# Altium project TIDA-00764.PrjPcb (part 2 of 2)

## Sheet TIDA-00764_Power_Stage.SchDoc: Power Stage
size 431 x 279 mm; Date: Not shown in title block; ApprovedBy: Not shown in title block; CheckedBy: Not shown in title block; Author: Not shown in title block; CompanyName: Not shown in title block; DrawnBy: Tobias Puetz; Engineer: Not shown in title block; Organization: Not shown in title block; Address1: Not shown in title block; Address2: Not shown in title block; Address3: Not shown in title block; Address4: Not shown in title block; DocumentNumber: 4; Revision: Use project parameter SCH_Rev; SheetNumber: 4; SheetTotal: 10; PageSetup: Record=PageOptions¦CenterHorizontal=True¦CenterVertical=True¦PrintScale=0.66¦XCorrection=1.00¦YCorrection=1.00¦PrintKind=0¦BorderSize=5000000¦LeftOffset=0¦BottomOffset=0¦Orientation=2¦PaperLength=1000¦PaperWidth=1000¦Scale=100¦PaperSource=15¦PrintQuality=600¦MediaType=1¦DitherType=10¦PrintScaleMode=1¦PaperKind=Letter
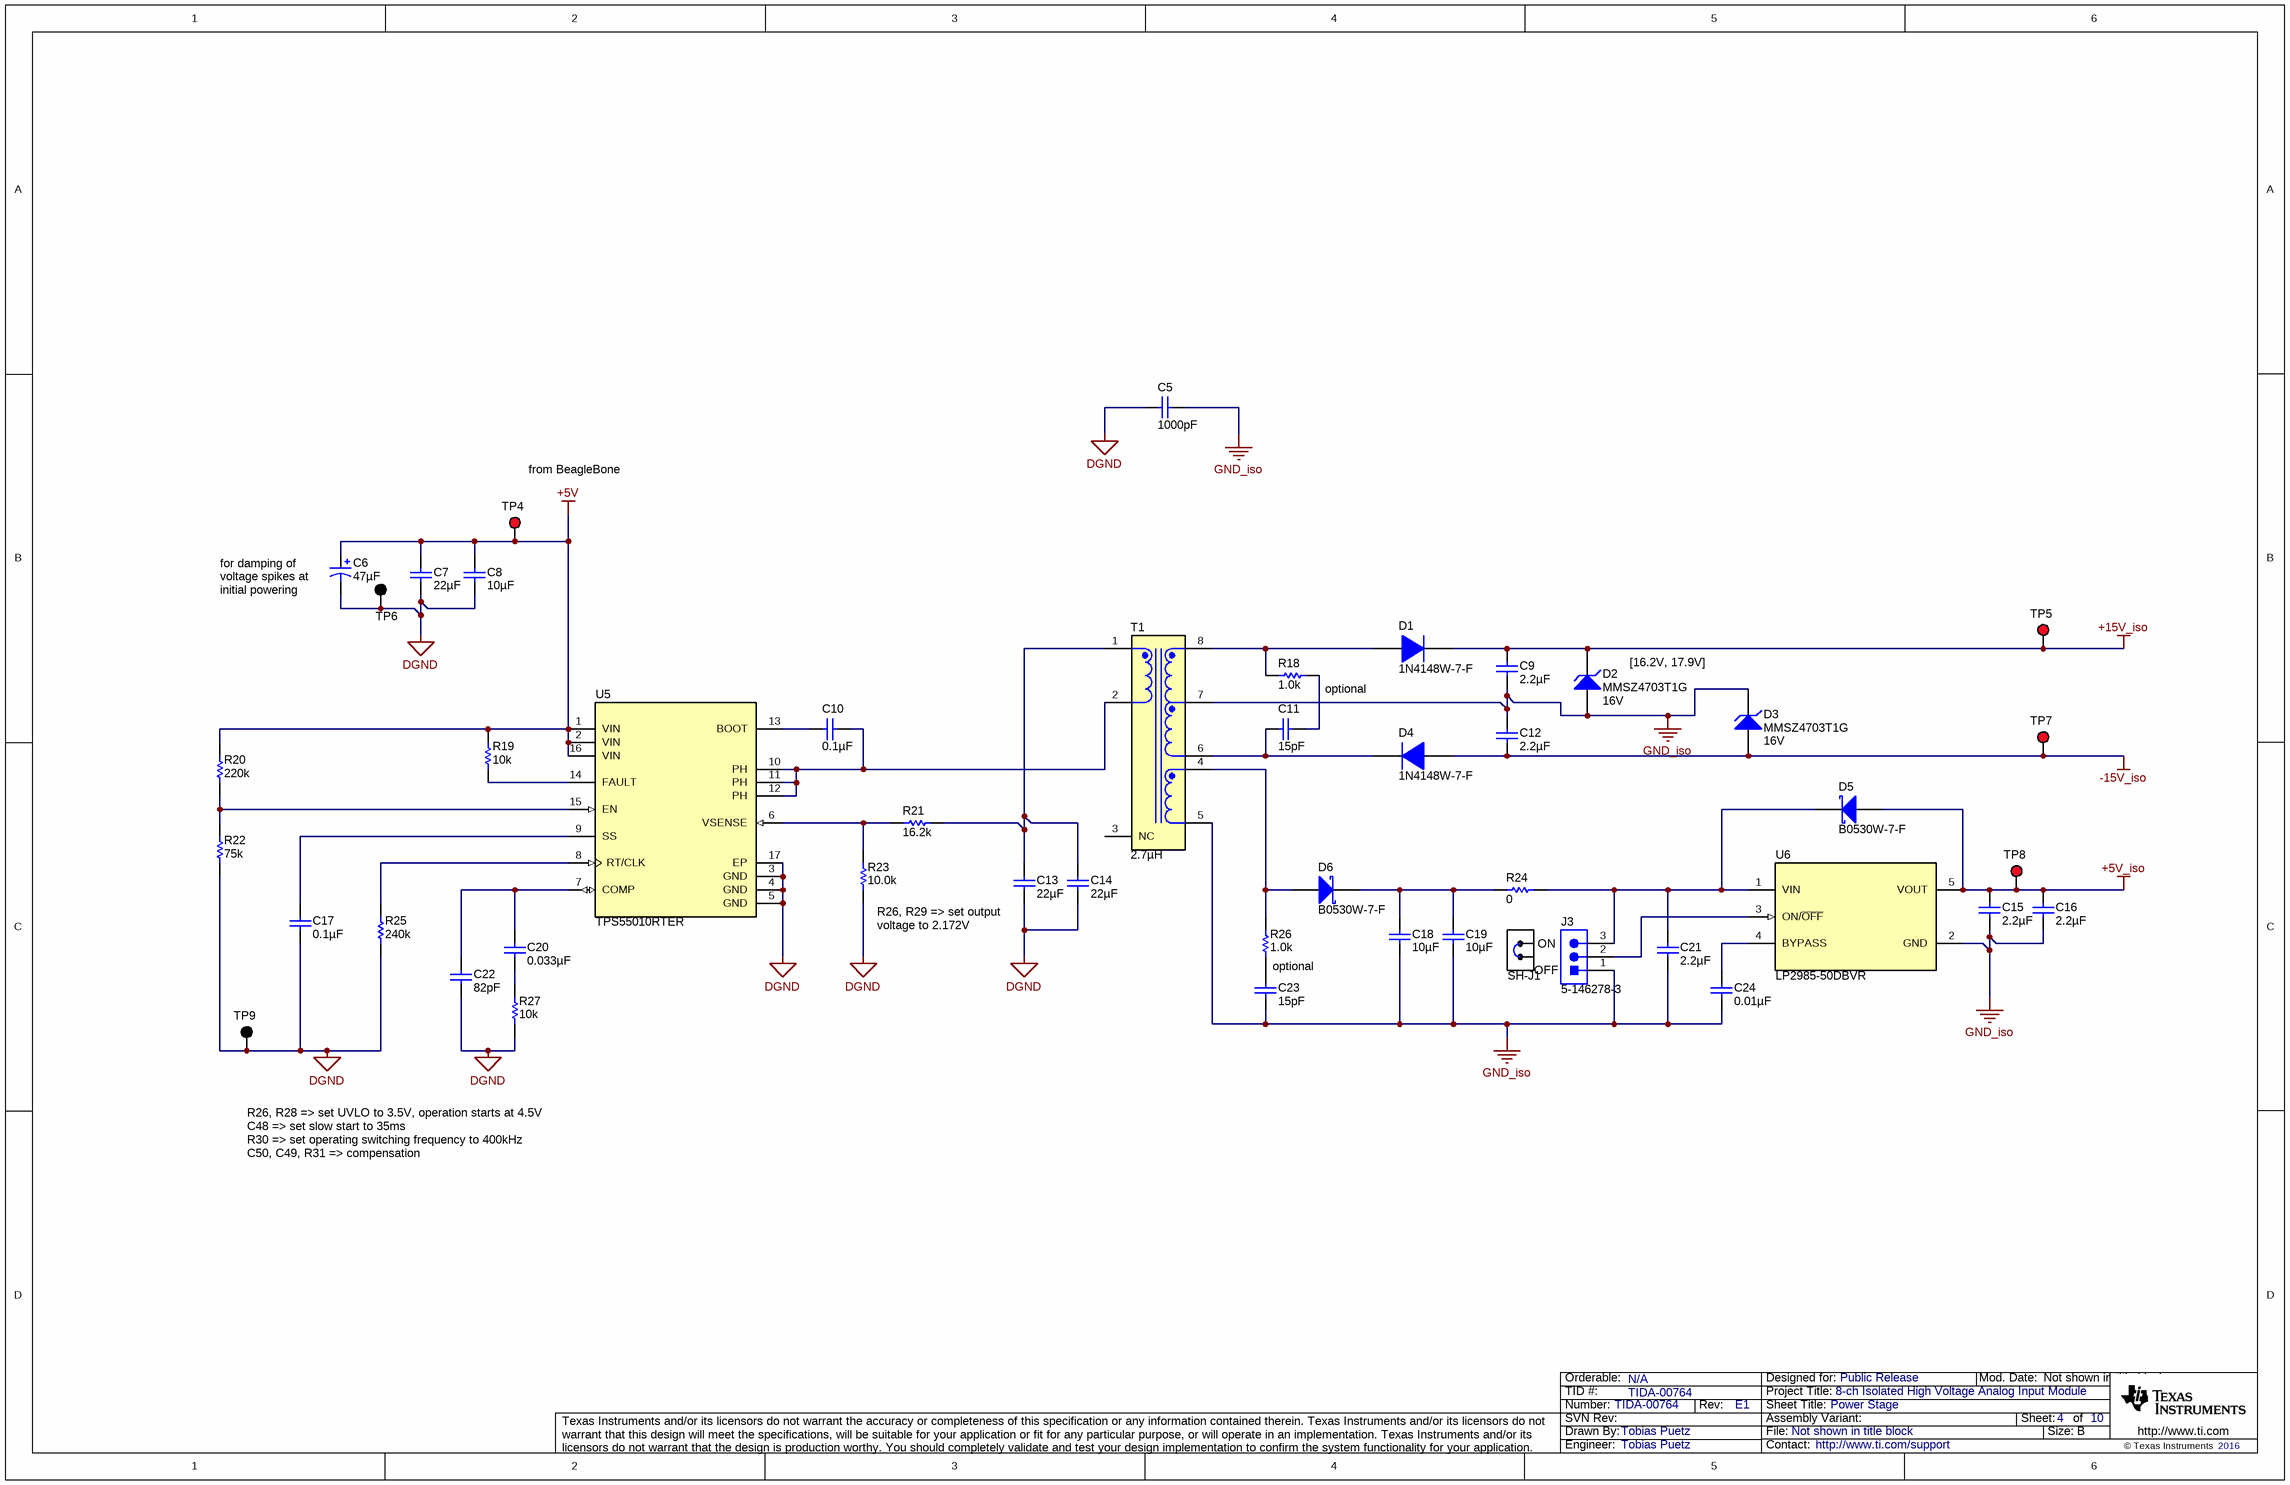
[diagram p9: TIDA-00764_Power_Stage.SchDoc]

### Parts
C5  ValueDisplayed: 1000pF  [1206_190]  (hidden comment: 202R18W102KV4E)
C6  ValueDisplayed: 47µF  [CAPPRD200W50D500H1100]  (hidden comment: ECA-1VM470)
C7  ValueDisplayed: 22µF  [1206_180]  (hidden comment: GRM31CR71A226KE15L)
C8  ValueDisplayed: 10µF  [0805_HV]  (hidden comment: C2012X7R1A106K125AC)
C9  ValueDisplayed: 2.2µF  [1206_180]  (hidden comment: GRM31CR71H225KA88L)
C10  ValueDisplayed: 0.1µF  [0603]  (hidden comment: C1608X7R1C104K)
C11  ValueDisplayed: 15pF  [0603]  (hidden comment: C1608C0G1H150J)
C12  ValueDisplayed: 2.2µF  [1206_180]  (hidden comment: GRM31CR71H225KA88L)
C13  ValueDisplayed: 22µF  [1206_180]  (hidden comment: GRM31CR71A226KE15L)
C14  ValueDisplayed: 22µF  [1206_180]  (hidden comment: GRM31CR71A226KE15L)
C15  ValueDisplayed: 2.2µF  [0603]  (hidden comment: GRM188R71A225KE15D)
C16  ValueDisplayed: 2.2µF  [0603]  (hidden comment: GRM188R71A225KE15D)
C17  ValueDisplayed: 0.1µF  [0603]  (hidden comment: C1608X7R1C104K)
C18  ValueDisplayed: 10µF  [0805_HV]  (hidden comment: C2012X7R1A106K125AC)
C19  ValueDisplayed: 10µF  [0805_HV]  (hidden comment: C2012X7R1A106K125AC)
C20  ValueDisplayed: 0.033µF  [0603]  (hidden comment: GRM188R71H333KA61D)
C21  ValueDisplayed: 2.2µF  [0603]  (hidden comment: GRM188R71A225KE15D)
C22  ValueDisplayed: 82pF  [0603]  (hidden comment: GRM1885C1H820JA01D)
C23  ValueDisplayed: 15pF  [0603]  (hidden comment: C1608C0G1H150J)
C24  ValueDisplayed: 0.01µF  [0603]  (hidden comment: GRM188R71C103KA01D)
D1  1N4148W-7-F  [SOD-123]
D2  MMSZ4703T1G  value 16V  [SOD-123]
D3  MMSZ4703T1G  value 16V  [SOD-123]
D4  1N4148W-7-F  [SOD-123]
D5  B0530W-7-F  [SOD-123]
D6  B0530W-7-F  [SOD-123]
J3  5-146278-3  [TE_5-146278-3]
R18  ValueDisplayed: 1.0k  [0805_HV]  (hidden comment: ERJ-6GEYJ102V)
R19  ValueDisplayed: 10k  [0603]  (hidden comment: CRCW060310K0JNEA)
R20  ValueDisplayed: 220k  [0603]  (hidden comment: CRCW0603220KJNEA)
R21  ValueDisplayed: 16.2k  [0603]  (hidden comment: CRCW060316K2FKEA)
R22  ValueDisplayed: 75k  [0603]  (hidden comment: CRCW060375K0JNEA)
R23  ValueDisplayed: 10.0k  [0603]  (hidden comment: CRCW060310K0FKEA)
R24  ValueDisplayed: 0  [0603]  (hidden comment: CRCW06030000Z0EA)
R25  ValueDisplayed: 240k  [0603]  (hidden comment: CRCW0603240KJNEA)
R26  ValueDisplayed: 1.0k  [0805_HV]  (hidden comment: ERJ-6GEYJ102V)
R27  ValueDisplayed: 10k  [0603]  (hidden comment: CRCW060310K0JNEA)
SH-J1  60900213421  [Wurth_60900213421]  (value not drawn)
T1  ValueDisplayed: 2.7µH  [Wurth_750316170]  (hidden comment: 750316170)
TP4  5000  [Keystone5000]  (value not drawn)
TP5  5000  [Keystone5000]  (value not drawn)
TP6  5001  [Keystone5001]  (value not drawn)
TP7  5000  [Keystone5000]  (value not drawn)
TP8  5000  [Keystone5000]  (value not drawn)
TP9  5001  [Keystone5001]  (value not drawn)
U5  TPS55010RTER  [RTE0016C]
U6  LP2985-50DBVR  [DBV0005A_N]

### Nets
+5V: C6.1(+) C7.1 C8.2 R19.2 R20.2 TP4.1 U5.1(VIN) U5.2(VIN) U5.16(VIN)
+5V_iso: C15.1 C16.1 D5.2(A) TP8.1 U6.5(VOUT)
+15V_iso: C9.1 D1.1(K) D2.1(K) TP5.1
-15V_iso: C12.2 D3.2(A) D4.2(A) TP7.1
DGND: C5.2 C6.2(-) C7.2 C8.1 C13.2 C14.2 C17.1 C22.1 R22.1 R23.1 R25.1 R27.1 TP6.1 TP9.1 U5.3(GND) U5.4(GND) U5.5(GND) U5.17(EP)
GND_iso: C5.1 C9.2 C12.1 C15.2 C16.2 C18.2 C19.1 C21.2 C23.1 C24.2 D2.2(A) D3.1(K) J3.1 T1.5 T1.7 U6.2(GND)
NetC10_1: C10.1 T1.2 U5.10(PH) U5.11(PH) U5.12(PH)
NetC10_2: C10.2 U5.13(BOOT)
NetC11_1: C11.1 R18.1
NetC11_2: C11.2 D4.1(K) T1.6
NetC13_1: C13.1 C14.1 R21.1 T1.1
NetC17_2: C17.2 U5.9(SS)
NetC18_1: C18.1 C19.2 D6.1(K) R24.1
NetC20_1: C20.1 C22.2 U5.7(COMP)
NetC20_2: C20.2 R27.2
NetC21_1: C21.1 D5.1(K) J3.3 R24.2 U6.1(VIN)
NetC23_2: C23.2 R26.1
NetC24_1: C24.1 U6.4(BYPASS)
NetD1_2: D1.2(A) R18.2 T1.8
NetD6_2: D6.2(A) R26.2 T1.4
NetJ3_2: J3.2 U6.3(ON/~{OFF})
NetR19_1: R19.1 U5.14(FAULT)
NetR20_1: R20.1 R22.2 U5.15(EN)
NetR21_2: R21.2 R23.2 U5.6(VSENSE)
NetR25_2: R25.2 U5.8(RT/CLK)

Not connected (* = marked no-connect by the designer): T1 3(NC)

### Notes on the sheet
- from BeagleBone
- (near C6) for damping of voltage spikes at initial powering
- (near R18) optional
- [16.2V, 17.9V]
- R26, R29 => set output voltage to 2.172V
- (near R26) optional
- ON
- OFF
- R26, R28 => set UVLO to 3.5V, operation starts at 4.5V
  C48 => set slow start to 35ms
  R30 => set operating switching frequency to 400kHz
  C50, C49, R31 => compensation

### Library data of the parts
C5 = 202R18W102KV4E: CAP, CERM, 1000 pF, 2000 V, +/- 10%, X7R, 1206_190; Manufacturer: Johanson Technology; Polarized: N; CompType: Capacitor; Value: 1000pF; U/M: EA; Cap_F: 0.000000001; Tolerance_%: 10; Value1: Unknown; VDC_V: 2000; Value2: 2000V; TaMin_C: -55; TaMax_C: 125; Cap_Case: 1206; AEC Category: Q200
C6 = ECA-1VM470: CAP, AL, 47 µF, 35 V, +/- 20%, TH; Manufacturer: Panasonic; Polarized: Y; CompType: Capacitor; Value: 47uF; U/M: EA; Cap_F: 0.000047; Tolerance_%: 20; Value1: Unknown; VDC_V: 35; Value2: 35V; IRMS_A: 0.13; TaMin_C: -40; TaMax_C: 85; Cap_Case: RCAP, 5x11mm; AEC Category: Q200; AEC Qualified: N
C7 C13 C14 = GRM31CR71A226KE15L: CAP, CERM, 22 µF, 10 V, +/- 10%, X7R, 1206; Manufacturer: MuRata; Polarized: N; CompType: Capacitor; Value: 22uF; U/M: EA; Cap_F: 0.000022; Tolerance_%: 10; Value1: Unknown; Value2: 10V; TaMin_C: -55; TaMax_C: 125; Cap_Case: 1206; AEC Category: Q200
C8 C18 C19 = C2012X7R1A106K125AC: CAP, CERM, 10 µF, 10 V, +/- 10%, X7R, 0805; Manufacturer: TDK; Polarized: N; CompType: Capacitor; Value: 10uF; U/M: EA; Cap_F: 0.00001; Tolerance_%: 10; Value1: Unknown; Value2: 10V; TaMin_C: -55; TaMax_C: 125; Cap_Case: 0805; AEC Category: Q200
C9 C12 = GRM31CR71H225KA88L: CAP, CERM, 2.2 µF, 50 V, +/- 10%, X7R, 1206; Manufacturer: MuRata; Polarized: N; CompType: Capacitor; Value: 2.2uF; U/M: EA; Cap_F: 0.0000022; Tolerance_%: 10; Value1: Unknown; VDC_V: 50; Value2: 50V; TaMin_C: -55; TaMax_C: 125; Cap_Case: 1206; AEC Category: Q200
C10 C17 = C1608X7R1C104K: CAP, CERM, 0.1 µF, 16 V, +/- 10%, X7R, 0603; Manufacturer: TDK; Polarized: N; CompType: Capacitor; Value: 0.1uF; U/M: EA; Cap_F: 0.0000001; Tolerance_%: 10; ESR_ohm: 0.017; Value1: 0.017 ohm; VDC_V: 16; Value2: 16V; TaMin_C: -55; TaMax_C: 125; AEC Category: Q200
C11 C23 = C1608C0G1H150J: CAP, CERM, 15 pF, 50 V, +/- 5%, C0G/NP0, 0603; Manufacturer: TDK; Polarized: N; CompType: Capacitor; Value: 15pF; U/M: EA; Cap_F: 0.000000000015; Tolerance_%: 5; ESR_ohm: 0.46; Value1: 0.46 ohm; VDC_V: 50; Value2: 50V; TaMin_C: -55; TaMax_C: 125; AEC Category: Q200
C15 C16 C21 = GRM188R71A225KE15D: CAP, CERM, 2.2 µF, 10 V, +/- 10%, X7R, 0603; Manufacturer: MuRata; Polarized: N; CompType: Capacitor; Value: 2.2uF; U/M: EA; Cap_F: 0.0000022; Tolerance_%: 10; ESR_ohm: 0.009; Value1: 0.009 ohm; Value2: 10V; TaMin_C: -55; TaMax_C: 125; AEC Category: Q200
C20 = GRM188R71H333KA61D: CAP, CERM, 0.033 µF, 50 V, +/- 10%, X7R, 0603; Manufacturer: MuRata; Polarized: N; CompType: Capacitor; Value: 0.033uF; U/M: EA; Cap_F: 0.000000033; Tolerance_%: 10; Value1: Unknown; VDC_V: 50; Value2: 50V; TaMin_C: -55; TaMax_C: 125; AEC Category: Q200
C22 = GRM1885C1H820JA01D: CAP, CERM, 82 pF, 50 V, +/- 5%, C0G/NP0, 0603; Manufacturer: MuRata; Polarized: N; CompType: Capacitor; Value: 82pF; U/M: EA; Cap_F: 0.000000000082; Tolerance_%: 5; Value1: Unknown; VDC_V: 50; Value2: 50V; TaMin_C: -55; TaMax_C: 125; AEC Category: Q200
C24 = GRM188R71C103KA01D: CAP, CERM, 0.01 µF, 16 V, +/- 10%, X7R, 0603; Manufacturer: MuRata; Polarized: N; CompType: Capacitor; Value: 0.01uF; U/M: EA; Cap_F: 0.00000001; Tolerance_%: 10; Value1: Unknown; VDC_V: 16; Value2: 16V; TaMin_C: -55; TaMax_C: 125; AEC Category: Q200
D1 D4 = 1N4148W-7-F: Diode, Ultrafast, 100 V, 0.15 A, SOD-123; Manufacturer: Diodes Inc.; U/M: EA; Vf_V: 1.25; Value: 100V; Value1: 0.15A; Value2: 1.25V; Io_A: 0.15; Vr_V: 100; TJmax_C: 150; AEC Category: Q101
D2 D3 = MMSZ4703T1G: Diode, Zener, 16 V, 500 mW, SOD-123; Manufacturer: ON Semiconductor; SymbolCreator: a0412235; U/M: EA; Power_W: 0.5; Vz_V: 16; Value1: 0.5W; RJA_CperW: 340; AEC Category: Q101
D5 D6 = B0530W-7-F: Diode, Schottky, 30 V, 0.5 A, SOD-123; Manufacturer: Diodes Inc.; U/M: EA; Vf_V: 0.43; Value: 30V; Value1: 0.5A; Value2: 0.43V; Io_A: 0.5; Vr_V: 30; TJmax_C: 125; AEC Category: Q101
J3 = 5-146278-3: Header, 100mil, 3x1, Tin, TH; Manufacturer: TE Connectivity; SymbolCreator: a0799628
R18 R26 = ERJ-6GEYJ102V: RES, 1.0 k, 5%, 0.125 W, 0805; Manufacturer: Panasonic; CompType: Resistor; Value: 1.0k; Res_ohm: 1000; Value_Code: 1k00; Tolerance_%: 5; Power_W: 0.125; Value2: 0.125W; VDC_V: 150; TempCo: 200 ppm/C; EIA_Code: E24; U/M: EA; AEC Category: Q200
R19 R27 = CRCW060310K0JNEA: RES, 10 k, 5%, 0.1 W, 0603; Manufacturer: Vishay-Dale; CompType: Resistor; Value: 10k; Res_ohm: 10000; Value_Code: 10k0; Tolerance_%: 5; Power_W: 0.1; Value2: 0.1W; VDC_V: 75; TempCo: 200 ppm/C; EIA_Code: E24; U/M: EA; AEC Category: Q200
R20 = CRCW0603220KJNEA: RES, 220 k, 5%, 0.1 W, 0603; Manufacturer: Vishay-Dale; CompType: Resistor; Value: 220k; Res_ohm: 220000; Tolerance_%: 5; Power_W: 0.1; Value2: 0.1W; VDC_V: 75; TempCo: 200 ppm/C; EIA_Code: E24; U/M: EA; AEC Category: Q200
R21 = CRCW060316K2FKEA: RES, 16.2 k, 1%, 0.1 W, 0603; Manufacturer: Vishay-Dale; CompType: Resistor; Value: 16.2k; Res_ohm: 16200; Value_Code: 16k2; Tolerance_%: 1; Power_W: 0.1; Value2: 0.1W; VDC_V: 75; TempCo: 100 ppm/C; EIA_Code: E96; U/M: EA; AEC Category: Q200
R22 = CRCW060375K0JNEA: RES, 75 k, 5%, 0.1 W, 0603; Manufacturer: Vishay-Dale; CompType: Resistor; Value: 75k; Res_ohm: 75000; Value_Code: 75k0; Tolerance_%: 5; Power_W: 0.1; Value2: 0.1W; VDC_V: 75; TempCo: 200 ppm/C; EIA_Code: E24; U/M: EA; AEC Category: Q200
R23 = CRCW060310K0FKEA: RES, 10.0 k, 1%, 0.1 W, 0603; Manufacturer: Vishay-Dale; CompType: Resistor; Value: 10.0k; Res_ohm: 10000; Value_Code: 10k0; Tolerance_%: 1; Power_W: 0.1; Value2: 0.1W; VDC_V: 75; TempCo: 100 ppm/C; EIA_Code: E96; U/M: EA; AEC Category: Q200
R24 = CRCW06030000Z0EA: RES, 0, 5%, 0.1 W, 0603; Manufacturer: Vishay-Dale; CompType: Resistor; Value: 0; Value_Code: 0000; Tolerance_%: 5; Power_W: 0.1; Value2: 0.1W; VDC_V: 75; TempCo: 200 ppm/C; EIA_Code: E24; U/M: EA; AEC Category: Q200
R25 = CRCW0603240KJNEA: RES, 240 k, 5%, 0.1 W, 0603; Manufacturer: Vishay-Dale; CompType: Resistor; Value: 240k; Res_ohm: 240000; Tolerance_%: 5; Power_W: 0.1; Value2: 0.1W; VDC_V: 75; TempCo: 200 ppm/C; EIA_Code: E24; U/M: EA; AEC Category: Q200
SH-J1 = 60900213421: Shunt, 2.54mm, Gold, Black; Manufacturer: Wurth Elektronik
T1 = 750316170: Transformer, 2.7 uH, SMT; Manufacturer: Wurth Elektronik; SymbolCreator: Altium; Value: 2.7uH; Lp: 2.7; DCR_ohm: 0.015; Ns1toNp: 8; Ns3toNp: 3; Rs1: 2.1; Rs3: 0.295
TP4 TP5 TP7 TP8 = 5000: Test Point, Miniature, Red, TH; Manufacturer: Keystone; CompType: Test Point Loop; ContactFinish: Silver
TP6 TP9 = 5001: Test Point, Miniature, Black, TH; Manufacturer: Keystone; CompType: Test Point Loop; ContactFinish: Silver
U5 = TPS55010RTER: 2.95V To 6V Input, 2W, Isolated DC/DC Converter with Integrated FETs, RTE0016C; Manufacturer: Texas Instruments; SymbolCreator: Altium; CompType: IC; U/M: EA
U6 = LP2985-50DBVR: 150-mA Low-noise Low-dropout Regulator With Shutdown, DBV0005A; Alternate PartNumber: LP2985-50DBVT; Manufacturer: Texas Instruments; SymbolCreator: Altium; CompType: IC; U/M: EA

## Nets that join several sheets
+5V: TIDA-00764_Cape (NT1.2), TIDA-00764_Digital_Isolation (6 pins), TIDA-00764_Power_Stage (9 pins)
+5V_iso: TIDA-00764_MUX_Stage (9 pins), TIDA-00764_Digital_Isolation (7 pins), TIDA-00764_Power_Stage (5 pins)
+15V_iso: U_TIDA-00764_Signal_Chain/Channel_Inputs/CMCh1 (C30_CMCh1.2 C31_CMCh1.1 U7_CMCh1.7), U_TIDA-00764_Signal_Chain/Channel_Inputs/CMCh3 (C30_CMCh3.2 C31_CMCh3.1 U7_CMCh3.7), U_TIDA-00764_Signal_Chain/Channel_Inputs/CMCh2 (C30_CMCh2.2 C31_CMCh2.1 U7_CMCh2.7), U_TIDA-00764_Signal_Chain/Channel_Inputs/CMCh4 (C30_CMCh4.2 C31_CMCh4.1 U7_CMCh4.7), TIDA-00764_MUX_Stage (C44.1 C45.2 U11.13 U13.5), TIDA-00764_Power_Stage (C9.1 D1.1 D2.1 TP5.1)
-15V_iso: U_TIDA-00764_Signal_Chain/Channel_Inputs/CMCh1 (C25_CMCh1.1 C26_CMCh1.2 U7_CMCh1.4), U_TIDA-00764_Signal_Chain/Channel_Inputs/CMCh3 (C25_CMCh3.1 C26_CMCh3.2 U7_CMCh3.4), U_TIDA-00764_Signal_Chain/Channel_Inputs/CMCh2 (C25_CMCh2.1 C26_CMCh2.2 U7_CMCh2.4), U_TIDA-00764_Signal_Chain/Channel_Inputs/CMCh4 (C25_CMCh4.1 C26_CMCh4.2 U7_CMCh4.4), TIDA-00764_MUX_Stage (C39.2 U11.3 U13.2), TIDA-00764_Power_Stage (C12.2 D3.2 D4.2 TP7.1)
DGND: TIDA-00764_Cape (21 pins), TIDA-00764_Digital_Isolation (7 pins), TIDA-00764_Power_Stage (18 pins)
GND_iso: TIDA-00764_Signal_Chain (5 pins), U_TIDA-00764_Signal_Chain/Channel_Inputs/CMCh1 (11 pins), U_TIDA-00764_Signal_Chain/Channel_Inputs/CMCh3 (11 pins), U_TIDA-00764_Signal_Chain/Channel_Inputs/CMCh2 (11 pins), U_TIDA-00764_Signal_Chain/Channel_Inputs/CMCh4 (11 pins), U_TIDA-00764_Signal_Chain/Channel_Inputs/NoCMCh1 (C32_NoCMCh1.2 D11_NoCMCh1.2 D12_NoCMCh1.1 R31_NoCMCh1.1), U_TIDA-00764_Signal_Chain/Channel_Inputs/NoCMCh2 (C32_NoCMCh2.2 D11_NoCMCh2.2 D12_NoCMCh2.1 R31_NoCMCh2.1), U_TIDA-00764_Signal_Chain/Channel_Inputs/NoCMCh3 (C32_NoCMCh3.2 D11_NoCMCh3.2 D12_NoCMCh3.1 R31_NoCMCh3.1), U_TIDA-00764_Signal_Chain/Channel_Inputs/NoCMCh4 (C32_NoCMCh4.2 D11_NoCMCh4.2 D12_NoCMCh4.1 R31_NoCMCh4.1), TIDA-00764_MUX_Stage (20 pins), TIDA-00764_Digital_Isolation (7 pins), TIDA-00764_Power_Stage (16 pins)
A0 / SER: TIDA-00764_Cape (R7.2 R8.2), TIDA-00764_Digital_Isolation (TP18.1 U10.5)
A0 / SER_iso: TIDA-00764_MUX_Stage (U15.6), TIDA-00764_Digital_Isolation (U10.12)
A1 / ~{RCLR}: TIDA-00764_Cape (R9.2 R10.2), TIDA-00764_Digital_Isolation (TP19.1 U10.4)
A1 / ~{RCLR}_iso: TIDA-00764_MUX_Stage (U15.10), TIDA-00764_Digital_Isolation (U10.13)
A2: TIDA-00764_Cape (R11.2 R12.2), TIDA-00764_Digital_Isolation (TP20.1 U10.3)
A2_iso: TIDA-00764_MUX_Stage (U11.15), TIDA-00764_Digital_Isolation (U10.14)
Ch_In+: TIDA-00764_Signal_Chain (J4.10), U_TIDA-00764_Signal_Chain/Channel_Inputs/NoCMCh4 (C32_NoCMCh4.1 D12_NoCMCh4.2 K2_NoCMCh4.3), TIDA-00764_MUX_Stage (R37.2)
Ch_In+: TIDA-00764_Signal_Chain (J4.11), U_TIDA-00764_Signal_Chain/Channel_Inputs/NoCMCh3 (C32_NoCMCh3.1 D12_NoCMCh3.2 K2_NoCMCh3.3), TIDA-00764_MUX_Stage (R38.2)
Ch_In+: TIDA-00764_Signal_Chain (J4.12), U_TIDA-00764_Signal_Chain/Channel_Inputs/NoCMCh2 (C32_NoCMCh2.1 D12_NoCMCh2.2 K2_NoCMCh2.3), TIDA-00764_MUX_Stage (R39.2)
Ch_In+: TIDA-00764_Signal_Chain (J4.13), U_TIDA-00764_Signal_Chain/Channel_Inputs/NoCMCh1 (C32_NoCMCh1.1 D12_NoCMCh1.2 K2_NoCMCh1.3), TIDA-00764_MUX_Stage (R40.2)
Ch_V/C_Switch: U_TIDA-00764_Signal_Chain/Channel_Inputs/NoCMCh1 (R30_NoCMCh1.2), TIDA-00764_MUX_Stage (U14.4)
Ch_V/C_Switch: U_TIDA-00764_Signal_Chain/Channel_Inputs/NoCMCh2 (R30_NoCMCh2.2), TIDA-00764_MUX_Stage (U14.5)
Ch_V/C_Switch: U_TIDA-00764_Signal_Chain/Channel_Inputs/NoCMCh3 (R30_NoCMCh3.2), TIDA-00764_MUX_Stage (U14.6)
Ch_V/C_Switch: U_TIDA-00764_Signal_Chain/Channel_Inputs/NoCMCh4 (R30_NoCMCh4.2), TIDA-00764_MUX_Stage (U14.7)
CMCh_In+: TIDA-00764_Signal_Chain (J4.5), U_TIDA-00764_Signal_Chain/Channel_Inputs/CMCh3 (6 pins)
CMCh_In+: TIDA-00764_Signal_Chain (J4.3), U_TIDA-00764_Signal_Chain/Channel_Inputs/CMCh4 (6 pins)
CMCh_In+: TIDA-00764_Signal_Chain (J4.7), U_TIDA-00764_Signal_Chain/Channel_Inputs/CMCh2 (6 pins)
CMCh_In+: TIDA-00764_Signal_Chain (J4.9), U_TIDA-00764_Signal_Chain/Channel_Inputs/CMCh1 (6 pins)
CMCh_In-: TIDA-00764_Signal_Chain (J4.4), U_TIDA-00764_Signal_Chain/Channel_Inputs/CMCh3 (6 pins)
CMCh_In-: TIDA-00764_Signal_Chain (J4.2), U_TIDA-00764_Signal_Chain/Channel_Inputs/CMCh4 (6 pins)
CMCh_In-: TIDA-00764_Signal_Chain (J4.6), U_TIDA-00764_Signal_Chain/Channel_Inputs/CMCh2 (6 pins)
CMCh_In-: TIDA-00764_Signal_Chain (J4.8), U_TIDA-00764_Signal_Chain/Channel_Inputs/CMCh1 (6 pins)
CMCh_Out: U_TIDA-00764_Signal_Chain/Channel_Inputs/CMCh1 (U7_CMCh1.6), TIDA-00764_MUX_Stage (R36.2)
CMCh_Out: U_TIDA-00764_Signal_Chain/Channel_Inputs/CMCh3 (U7_CMCh3.6), TIDA-00764_MUX_Stage (R34.2)
CMCh_Out: U_TIDA-00764_Signal_Chain/Channel_Inputs/CMCh2 (U7_CMCh2.6), TIDA-00764_MUX_Stage (R35.2)
CMCh_Out: U_TIDA-00764_Signal_Chain/Channel_Inputs/CMCh4 (U7_CMCh4.6), TIDA-00764_MUX_Stage (R32.2)
CMCh_V/C_Switch: U_TIDA-00764_Signal_Chain/Channel_Inputs/CMCh1 (R28_CMCh1.2), TIDA-00764_MUX_Stage (U14.15)
CMCh_V/C_Switch: U_TIDA-00764_Signal_Chain/Channel_Inputs/CMCh3 (R28_CMCh3.2), TIDA-00764_MUX_Stage (U14.2)
CMCh_V/C_Switch: U_TIDA-00764_Signal_Chain/Channel_Inputs/CMCh2 (R28_CMCh2.2), TIDA-00764_MUX_Stage (U14.1)
CMCh_V/C_Switch: U_TIDA-00764_Signal_Chain/Channel_Inputs/CMCh4 (R28_CMCh4.2), TIDA-00764_MUX_Stage (U14.3)
CONVST/~{CS}_iso: TIDA-00764_MUX_Stage (U12.11), TIDA-00764_Digital_Isolation (U9.13)
IN1+IN2: TIDA-00764_Cape (R5.2 R6.2), TIDA-00764_Digital_Isolation (TP17.1 U10.6)
IN1+IN2_iso: TIDA-00764_MUX_Stage (U12.9 U15.1 U15.5), TIDA-00764_Digital_Isolation (U10.11)
SCLK_iso: TIDA-00764_MUX_Stage (U12.12), TIDA-00764_Digital_Isolation (U9.12)
SDI_iso: TIDA-00764_MUX_Stage (U12.10), TIDA-00764_Digital_Isolation (U9.14)
SDO1_iso: TIDA-00764_MUX_Stage (U12.13), TIDA-00764_Digital_Isolation (U9.11)
SPI_CLK: TIDA-00764_Cape (J1.31), TIDA-00764_Digital_Isolation (TP14.1 U9.5)
SPI_CSa: TIDA-00764_Cape (U2.4), TIDA-00764_Digital_Isolation (TP15.1 U9.4)
SPI_MISO: TIDA-00764_Cape (J1.29), TIDA-00764_Digital_Isolation (TP13.1 U9.6)
SPI_MOSI: TIDA-00764_Cape (J1.30), TIDA-00764_Digital_Isolation (TP16.1 U9.3)

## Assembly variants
001: not fitted U8
002: all parts fitted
